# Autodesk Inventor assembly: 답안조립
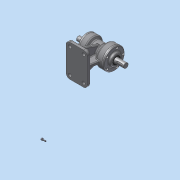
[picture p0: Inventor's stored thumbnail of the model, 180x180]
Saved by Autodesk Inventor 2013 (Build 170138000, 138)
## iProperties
Created: 2015-08
Part Number: 답안조립
Document SubType Name: Assembly
Designer: WINDOWS7
Author: WINDOWS7
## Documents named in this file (10)
- C:\Users\WINDOWS7\Desktop\450806V1031\답안조립.iam
- C:\Users\WINDOWS7\Desktop\450806V1031\M4x0.5.ipt
- C:\Users\WINDOWS7\Desktop\450806V1031\뒤커버.ipt
- C:\Users\WINDOWS7\Desktop\450806V1031\베어링 6203.ipt
- C:\Users\WINDOWS7\Desktop\450806V1031\베어링 6205.ipt
- C:\Users\WINDOWS7\Desktop\450806V1031\본체.ipt
- C:\Users\WINDOWS7\Desktop\450806V1031\앞커버.ipt
- C:\Users\WINDOWS7\Desktop\450806V1031\오일실 .ipt
- 오일실 .ipt
- C:\Users\WINDOWS7\Desktop\450806V1031\축.ipt
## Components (1 placed, 1 different names)
1. M4x0.5:1
